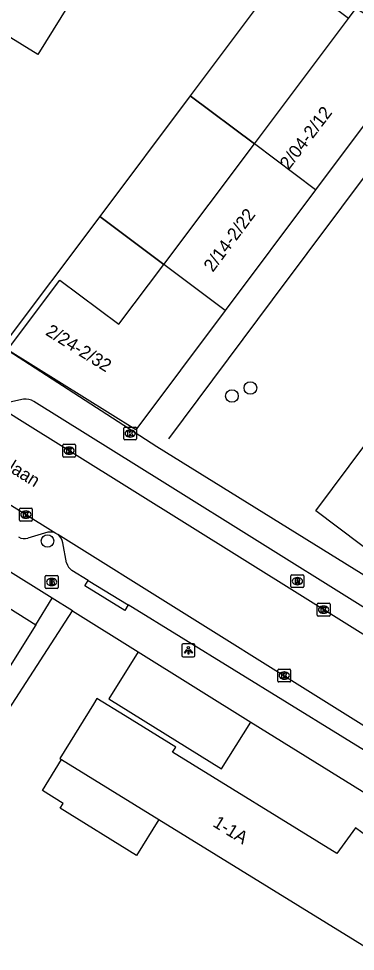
# Model space of a CAD drawing. Extents: x 160107 to 160928, y 382056 to 382918.
# Drawn here: x 160634.2 to 160660.5, y 382444.7 to 382517.3 of the extents above; entities that cross this region are included whole.
import ezdxf

# ---------------------------------------------------------------- set-up
doc = ezdxf.new("R2010")
doc.units = 0
for name, color, linetype in [('IMGEO_Boom', 7, 'Continuous'), ('IMGEO_Brandkraan', 7, 'Continuous'), ('IMGEO_Kolk', 7, 'Continuous'), ('IMGEO_Lichtpunt', 7, 'Continuous'), ('IMGEO_Lijnafwatering', 7, 'Continuous'), ('IMGEO_Openbare_ruimte_label', 7, 'Continuous'), ('IMGEO_Pand', 7, 'Continuous'), ('IMGEO_Pand_nummerreeks', 7, 'Continuous'), ('IMGEO_Pand_overbouw', 7, 'Continuous'), ('IMGEO_Rijbaan_lokaal_open', 7, 'Continuous'), ('IMGEO_Rioolput', 7, 'Continuous'), ('IMGEO_Voetpad_open', 7, 'Continuous')]:
    doc.layers.add(name, color=color, linetype=linetype)

msp = doc.modelspace()

# ---------------------------------------------------------------- linework, layer by layer
at = {"layer": 'IMGEO_Boom'}
for centre in [(160652.272, 382488.556), (160650.828, 382487.928), (160636.455, 382476.634)]:
    msp.add_circle(centre, 0.489, dxfattribs=at)
at = {"layer": 'IMGEO_Brandkraan'}
for p, q in [((160636.278, 382473.007), (160636.278, 382473.859)), ((160636.353, 382473.933), (160637.205, 382473.933)), ((160636.766, 382473.713), (160636.791, 382473.713)), ((160637.279, 382473.859), (160637.279, 382473.007)), ((160637.205, 382472.933), (160636.353, 382472.933)), ((160636.789, 382473.153), (160636.764, 382473.153))]:
    msp.add_line(p, q, dxfattribs=at)
for points in [[(160636.278, 382473.007), (160636.278, 382473.859)], [(160636.353, 382473.933), (160637.205, 382473.933)], [(160636.626, 382473.633), (160636.626, 382473.233), (160636.839, 382473.233)], [(160636.857, 382473.633), (160636.626, 382473.633)], [(160636.805, 382473.552), (160636.751, 382473.552), (160636.751, 382473.476)], [(160636.751, 382473.476), (160636.804, 382473.476)], [(160636.813, 382473.4), (160636.751, 382473.4), (160636.751, 382473.319)], [(160636.751, 382473.319), (160636.813, 382473.319)], [(160637.279, 382473.859), (160637.279, 382473.007)], [(160637.205, 382472.933), (160636.353, 382472.933)]]:
    msp.add_lwpolyline(points, dxfattribs=at)
for centre, radius, start, end in [((160636.355, 382473.857), 0.0765, 91.55205, 178.44795), ((160636.355, 382473.857), 0.0765, 91.55205, 178.44795), ((160636.806, 382473.514), 0.0379, 267.82845, 90.93552), ((160636.814, 382473.359), 0.0404, 269.87594, 90.50774), ((160636.861, 382473.488), 0.145, 59.4692, 91.53667), ((160636.886, 382473.535), 0.0922, 285.51372, 58.15012), ((160636.891, 382473.343), 0.105, 301.31148, 78.98903), ((160637.203, 382473.857), 0.0765, 1.55205, 88.44795), ((160637.203, 382473.857), 0.0765, 1.55205, 88.44795), ((160636.355, 382473.009), 0.0765, 181.55205, 268.44795), ((160636.355, 382473.009), 0.0765, 181.55205, 268.44795), ((160636.845, 382473.484), 0.251, 268.66757, 293.53466), ((160637.203, 382473.009), 0.0765, 271.55205, 358.44795), ((160637.203, 382473.009), 0.0765, 271.55205, 358.44795)]:
    msp.add_arc(centre, radius, start, end, dxfattribs=at)
for centre, major_axis, ratio, start_param, end_param in [((160636.765, 382473.433), (-0.387, 0.002), 0.722429, 4.712389, 7.853982), ((160636.79, 382473.433), (-0.39, 0.002), 0.717154, 1.570796, 4.712389)]:
    msp.add_ellipse(centre, major_axis=major_axis, ratio=ratio, start_param=start_param, end_param=end_param, dxfattribs=at)
at = {"layer": 'IMGEO_Kolk'}
for p, q in [((160642.398, 382484.582), (160642.398, 382485.434)), ((160642.473, 382485.508), (160643.325, 382485.508)), ((160642.886, 382485.288), (160642.911, 382485.288)), ((160643.399, 382485.434), (160643.399, 382484.582)), ((160643.325, 382484.508), (160642.473, 382484.508)), ((160642.909, 382484.728), (160642.884, 382484.728)), ((160637.641, 382483.241), (160637.641, 382484.093)), ((160637.716, 382484.167), (160638.568, 382484.167)), ((160638.129, 382483.947), (160638.154, 382483.947)), ((160638.642, 382484.093), (160638.642, 382483.241)), ((160638.568, 382483.167), (160637.716, 382483.167)), ((160638.152, 382483.387), (160638.127, 382483.387)), ((160634.266, 382478.263), (160634.266, 382479.115)), ((160634.341, 382479.189), (160635.193, 382479.189)), ((160635.267, 382479.115), (160635.267, 382478.263)), ((160634.777, 382478.409), (160634.752, 382478.409)), ((160634.754, 382478.969), (160634.779, 382478.969)), ((160635.193, 382478.189), (160634.341, 382478.189)), ((160657.478, 382470.854), (160657.478, 382471.706)), ((160657.553, 382471.78), (160658.405, 382471.78)), ((160657.966, 382471.56), (160657.991, 382471.56)), ((160658.479, 382471.706), (160658.479, 382470.854)), ((160658.405, 382470.78), (160657.553, 382470.78)), ((160657.989, 382471), (160657.964, 382471)), ((160654.404, 382465.72), (160654.404, 382466.572)), ((160654.479, 382466.646), (160655.331, 382466.646)), ((160654.892, 382466.426), (160654.917, 382466.426)), ((160655.405, 382466.572), (160655.405, 382465.72)), ((160655.331, 382465.646), (160654.479, 382465.646)), ((160654.915, 382465.866), (160654.89, 382465.866))]:
    msp.add_line(p, q, dxfattribs=at)
for points in [[(160642.398, 382484.582), (160642.398, 382485.434)], [(160642.473, 382485.508), (160643.325, 382485.508)], [(160642.719, 382485.208), (160642.842, 382485.208), (160642.842, 382485.057), (160642.972, 382485.208), (160643.136, 382485.208), (160642.99, 382485.057), (160643.143, 382484.808), (160642.991, 382484.808), (160642.906, 382484.972), (160642.842, 382484.905), (160642.842, 382484.808), (160642.719, 382484.808), (160642.719, 382485.208)], [(160643.399, 382485.434), (160643.399, 382484.582)], [(160643.325, 382484.508), (160642.473, 382484.508)], [(160637.641, 382483.241), (160637.641, 382484.093)], [(160637.716, 382484.167), (160638.568, 382484.167)], [(160637.962, 382483.867), (160638.085, 382483.867), (160638.085, 382483.716), (160638.215, 382483.867), (160638.379, 382483.867), (160638.233, 382483.716), (160638.386, 382483.467), (160638.234, 382483.467), (160638.149, 382483.631), (160638.085, 382483.564), (160638.085, 382483.467), (160637.962, 382483.467), (160637.962, 382483.867)], [(160638.642, 382484.093), (160638.642, 382483.241)], [(160638.568, 382483.167), (160637.716, 382483.167)], [(160634.266, 382478.263), (160634.266, 382479.115)], [(160634.341, 382479.189), (160635.193, 382479.189)], [(160635.267, 382479.115), (160635.267, 382478.263)], [(160634.587, 382478.889), (160634.71, 382478.889), (160634.71, 382478.738), (160634.84, 382478.889), (160635.004, 382478.889), (160634.858, 382478.738), (160635.011, 382478.489), (160634.859, 382478.489), (160634.774, 382478.653), (160634.71, 382478.586), (160634.71, 382478.489), (160634.587, 382478.489), (160634.587, 382478.889)], [(160635.193, 382478.189), (160634.341, 382478.189)], [(160657.478, 382470.854), (160657.478, 382471.706)], [(160657.553, 382471.78), (160658.405, 382471.78)], [(160657.799, 382471.48), (160657.922, 382471.48), (160657.922, 382471.329), (160658.052, 382471.48), (160658.216, 382471.48), (160658.07, 382471.329), (160658.223, 382471.08), (160658.071, 382471.08), (160657.986, 382471.244), (160657.922, 382471.177), (160657.922, 382471.08), (160657.799, 382471.08), (160657.799, 382471.48)], [(160658.479, 382471.706), (160658.479, 382470.854)], [(160658.405, 382470.78), (160657.553, 382470.78)], [(160654.404, 382465.72), (160654.404, 382466.572)], [(160654.479, 382466.646), (160655.331, 382466.646)], [(160654.725, 382466.346), (160654.848, 382466.346), (160654.848, 382466.195), (160654.978, 382466.346), (160655.142, 382466.346), (160654.996, 382466.195), (160655.149, 382465.946), (160654.997, 382465.946), (160654.912, 382466.11), (160654.848, 382466.043), (160654.848, 382465.946), (160654.725, 382465.946), (160654.725, 382466.346)], [(160655.405, 382466.572), (160655.405, 382465.72)], [(160655.331, 382465.646), (160654.479, 382465.646)]]:
    msp.add_lwpolyline(points, dxfattribs=at)
for centre, start, end in [((160642.475, 382485.432), 91.55205, 178.44795), ((160642.475, 382485.432), 91.55205, 178.44795), ((160643.323, 382485.432), 1.55205, 88.44795), ((160643.323, 382485.432), 1.55205, 88.44795), ((160642.475, 382484.584), 181.55205, 268.44795), ((160642.475, 382484.584), 181.55205, 268.44795), ((160643.323, 382484.584), 271.55205, 358.44795), ((160643.323, 382484.584), 271.55205, 358.44795), ((160637.718, 382484.091), 91.55205, 178.44795), ((160637.718, 382484.091), 91.55205, 178.44795), ((160638.566, 382484.091), 1.55205, 88.44795), ((160638.566, 382484.091), 1.55205, 88.44795), ((160637.718, 382483.243), 181.55205, 268.44795), ((160637.718, 382483.243), 181.55205, 268.44795), ((160638.566, 382483.243), 271.55205, 358.44795), ((160638.566, 382483.243), 271.55205, 358.44795), ((160634.343, 382479.113), 91.55205, 178.44795), ((160634.343, 382479.113), 91.55205, 178.44795), ((160635.191, 382479.113), 1.55205, 88.44795), ((160635.191, 382479.113), 1.55205, 88.44795), ((160634.343, 382478.265), 181.55205, 268.44795), ((160634.343, 382478.265), 181.55205, 268.44795), ((160635.191, 382478.265), 271.55205, 358.44795), ((160635.191, 382478.265), 271.55205, 358.44795), ((160657.555, 382471.704), 91.55205, 178.44795), ((160657.555, 382471.704), 91.55205, 178.44795), ((160658.403, 382471.704), 1.55205, 88.44795), ((160658.403, 382471.704), 1.55205, 88.44795), ((160657.555, 382470.856), 181.55205, 268.44795), ((160657.555, 382470.856), 181.55205, 268.44795), ((160658.403, 382470.856), 271.55205, 358.44795), ((160658.403, 382470.856), 271.55205, 358.44795), ((160654.481, 382466.57), 91.55205, 178.44795), ((160654.481, 382466.57), 91.55205, 178.44795), ((160655.329, 382466.57), 1.55205, 88.44795), ((160655.329, 382466.57), 1.55205, 88.44795), ((160654.481, 382465.722), 181.55205, 268.44795), ((160654.481, 382465.722), 181.55205, 268.44795), ((160655.329, 382465.722), 271.55205, 358.44795), ((160655.329, 382465.722), 271.55205, 358.44795)]:
    msp.add_arc(centre, 0.0765, start, end, dxfattribs=at)
for centre, major_axis, ratio, start_param, end_param in [((160642.885, 382485.008), (-0.387, 0.002), 0.722429, 4.712389, 7.853982), ((160642.91, 382485.008), (-0.39, 0.002), 0.717154, 1.570796, 4.712389), ((160638.128, 382483.667), (-0.387, 0.002), 0.722429, 4.712389, 7.853982), ((160638.153, 382483.667), (-0.39, 0.002), 0.717154, 1.570796, 4.712389), ((160634.753, 382478.689), (-0.387, 0.002), 0.722429, 4.712389, 7.853982), ((160634.778, 382478.689), (-0.39, 0.002), 0.717154, 1.570796, 4.712389), ((160657.965, 382471.28), (-0.387, 0.002), 0.722429, 4.712389, 7.853982), ((160657.99, 382471.28), (-0.39, 0.002), 0.717154, 1.570796, 4.712389), ((160654.891, 382466.146), (-0.387, 0.002), 0.722429, 4.712389, 7.853982), ((160654.916, 382466.146), (-0.39, 0.002), 0.717154, 1.570796, 4.712389)]:
    msp.add_ellipse(centre, major_axis=major_axis, ratio=ratio, start_param=start_param, end_param=end_param, dxfattribs=at)
at = {"layer": 'IMGEO_Lichtpunt'}
for p, q in [((160646.935, 382468.517), (160646.935, 382467.71)), ((160646.935, 382468.517), (160646.935, 382467.71)), ((160647.837, 382468.612), (160647.029, 382468.612)), ((160647.837, 382468.612), (160647.029, 382468.612)), ((160647.931, 382467.71), (160647.931, 382468.517)), ((160647.931, 382467.71), (160647.931, 382468.517)), ((160647.029, 382467.616), (160647.837, 382467.616)), ((160647.029, 382467.616), (160647.837, 382467.616))]:
    msp.add_line(p, q, dxfattribs=at)
for points in [[(160647.309, 382468.181), (160647.348, 382468.153), (160647.16, 382467.891), (160647.122, 382467.918), (160647.309, 382468.181)], [(160647.411, 382468.133), (160647.458, 382468.133), (160647.458, 382467.811), (160647.411, 382467.811), (160647.411, 382468.133)], [(160647.521, 382468.153), (160647.559, 382468.18), (160647.746, 382467.918), (160647.707, 382467.89), (160647.521, 382468.153)]]:
    msp.add_lwpolyline(points, dxfattribs=at)
msp.add_circle((160647.434, 382468.315), 0.0994, dxfattribs=at)
for centre, start, end in [((160647.029, 382468.517), 90, 180), ((160647.029, 382468.517), 90, 180), ((160647.837, 382468.517), 0, 90), ((160647.837, 382468.517), 0, 90), ((160647.029, 382467.71), 180, 270), ((160647.029, 382467.71), 180, 270), ((160647.837, 382467.71), 270, 0), ((160647.837, 382467.71), 270, 360)]:
    msp.add_arc(centre, 0.0946, start, end, dxfattribs=at)
at = {"layer": 'IMGEO_Lijnafwatering'}
for points in [[(160654, 382495.426), (160662.091, 382506.254)], [(160645.91, 382484.597), (160654, 382495.426)]]:
    msp.add_lwpolyline(points, dxfattribs=at)
at = {"layer": 'IMGEO_Pand'}
for points in [[(160639.295, 382520.324), (160635.687, 382514.541), (160633.257, 382516.056), (160631.03, 382517.445), (160622.018, 382503.2), (160622.561, 382502.857), (160622.454, 382502.688), (160623.206, 382502.212), (160623.035, 382501.942), (160616.467, 382506.097), (160618.877, 382509.909), (160617.058, 382511.061), (160621.744, 382518.47)], [(160652.582, 382507.572), (160659.926, 382517.347), (160660.526, 382518.146), (160665.515, 382514.919)], [(160662.14, 382510.411), (160657.342, 382504.002)], [(160645.524, 382498.178), (160652.582, 382507.572)], [(160657.342, 382504.002), (160652.582, 382507.572)], [(160657.342, 382504.002), (160650.301, 382494.596)], [(160650.301, 382494.596), (160643.343, 382485.301), (160633.336, 382491.531), (160637.422, 382496.967), (160642.026, 382493.523), (160645.524, 382498.178)], [(160650.301, 382494.596), (160645.524, 382498.178)], [(160667.761, 382492.911), (160677.503, 382485.613), (160681.492, 382482.598), (160673.677, 382472.259), (160667.015, 382477.296), (160664.325, 382473.736), (160657.378, 382478.987), (160667.761, 382492.911)], [(160630.808, 382473.047), (160635.54, 382470.101)], [(160635.54, 382470.101), (160632.891, 382465.866), (160630.784, 382462.498), (160629.877, 382461.047)], [(160643.528, 382467.993), (160641.229, 382464.322), (160650.03, 382458.884), (160652.296, 382462.502)], [(160643.528, 382467.993), (160652.296, 382462.502)], [(160664.677, 382454.86), (160662.926, 382452.473), (160660.47, 382454.274), (160659.015, 382452.289), (160646.208, 382460.179), (160646.451, 382460.573), (160642.506, 382463.004), (160640.309, 382464.367), (160640.037, 382463.924), (160637.426, 382459.686), (160637.554, 382459.607)], [(160645.131, 382454.939), (160643.4, 382452.129), (160637.44, 382455.801), (160637.676, 382456.184), (160636.059, 382457.181), (160637.554, 382459.607)], [(160637.554, 382459.607), (160645.131, 382454.939)], [(160645.131, 382454.939), (160666.802, 382441.589)]]:
    msp.add_lwpolyline(points, dxfattribs=at)
at = {"layer": 'IMGEO_Pand_overbouw'}
for points in [[(160652.582, 382507.572), (160659.926, 382517.347), (160654.91, 382521.109), (160647.574, 382511.327)], [(160652.582, 382507.572), (160647.574, 382511.327), (160640.525, 382501.927), (160645.524, 382498.178)], [(160633.336, 382491.531), (160637.422, 382496.967), (160642.026, 382493.523), (160645.524, 382498.178), (160640.525, 382501.927), (160632.911, 382491.774)]]:
    msp.add_lwpolyline(points, close=True, dxfattribs=at)
at = {"layer": 'IMGEO_Rijbaan_lokaal_open'}
for points in [[(160637.113, 382477.217), (160615.673, 382490.566)], [(160631.794, 382487.669), (160634.056, 382486.236), (160669.392, 382464.183)], [(160637.252, 382477.13), (160637.113, 382477.217)], [(160666.192, 382459.055), (160637.252, 382477.13)]]:
    msp.add_lwpolyline(points, dxfattribs=at)
at = {"layer": 'IMGEO_Rioolput'}
for p, q in [((160655.43, 382473.073), (160655.43, 382473.925)), ((160655.505, 382473.999), (160656.357, 382473.999)), ((160655.918, 382473.779), (160655.943, 382473.779)), ((160656.431, 382473.925), (160656.431, 382473.073)), ((160656.357, 382472.999), (160655.505, 382472.999)), ((160655.941, 382473.219), (160655.916, 382473.219))]:
    msp.add_line(p, q, dxfattribs=at)
for points in [[(160655.43, 382473.073), (160655.43, 382473.925)], [(160655.505, 382473.999), (160656.357, 382473.999)], [(160656.019, 382473.697), (160655.767, 382473.699), (160655.767, 382473.299)], [(160655.767, 382473.299), (160655.891, 382473.299), (160655.891, 382473.461), (160655.902, 382473.461)], [(160655.945, 382473.618), (160655.891, 382473.618), (160655.891, 382473.537)], [(160655.891, 382473.537), (160655.943, 382473.537)], [(160655.949, 382473.432), (160656.02, 382473.299), (160656.16, 382473.299), (160656.095, 382473.425)], [(160656.431, 382473.925), (160656.431, 382473.073)], [(160656.357, 382472.999), (160655.505, 382472.999)]]:
    msp.add_lwpolyline(points, dxfattribs=at)
for centre, radius, start, end in [((160655.507, 382473.923), 0.0765, 91.55205, 178.44795), ((160655.507, 382473.923), 0.0765, 91.55205, 178.44795), ((160655.901, 382473.408), 0.0533, 26.02933, 88.69889), ((160655.927, 382473.726), 0.19, 274.7715, 282.96867), ((160655.951, 382473.522), 0.0964, 77.00612, 93.18647), ((160655.965, 382473.579), 0.0378, 276.66336, 79.67722), ((160656.018, 382473.587), 0.109, 350.36119, 89.41601), ((160656.016, 382473.587), 0.112, 277.58423, 350.98172), ((160656, 382473.372), 0.108, 29.51342, 73.79051), ((160656.355, 382473.923), 0.0765, 1.55205, 88.44795), ((160656.355, 382473.923), 0.0765, 1.55205, 88.44795), ((160655.507, 382473.075), 0.0765, 181.55205, 268.44795), ((160655.507, 382473.075), 0.0765, 181.55205, 268.44795), ((160656.355, 382473.075), 0.0765, 271.55205, 358.44795), ((160656.355, 382473.075), 0.0765, 271.55205, 358.44795)]:
    msp.add_arc(centre, radius, start, end, dxfattribs=at)
for centre, major_axis, ratio, start_param, end_param in [((160655.917, 382473.499), (-0.387, 0.002), 0.722429, 4.712389, 7.853982), ((160655.942, 382473.499), (-0.39, 0.002), 0.717154, 1.570796, 4.712389)]:
    msp.add_ellipse(centre, major_axis=major_axis, ratio=ratio, start_param=start_param, end_param=end_param, dxfattribs=at)
at = {"layer": 'IMGEO_Voetpad_open'}
for points in [[(160636.83, 382472.17), (160592.202, 382500), (160588.519, 382502.294), (160565.683, 382503.748)], [(160620.525, 382499.569), (160632.911, 382491.774), (160644.968, 382483.985), (160680.935, 382461.701)], [(160634.592, 382487.675), (160633.277, 382487.396)], [(160667.829, 382467.255), (160645.589, 382481.125), (160635.377, 382487.506)], [(160636.472, 382477.312), (160634.933, 382476.85)], [(160637.947, 382474.938), (160637.646, 382476.479)], [(160639.623, 382473.562), (160638.362, 382474.339)], [(160642.736, 382471.644), (160642.474, 382471.219), (160639.361, 382473.137), (160639.623, 382473.562)], [(160639.623, 382473.562), (160642.736, 382471.644)], [(160635.54, 382470.101), (160636.83, 382472.17)], [(160638.41, 382471.185), (160636.83, 382472.17)], [(160630.34, 382458.764), (160638.41, 382471.185)], [(160638.41, 382471.185), (160643.528, 382467.993)], [(160663.389, 382458.917), (160642.736, 382471.644)], [(160652.296, 382462.502), (160664.677, 382454.86)]]:
    msp.add_lwpolyline(points, dxfattribs=at)
for centre, radius, start, end in [((160634.771, 382486.599), 1.091, 56.24854, 99.45231), ((160634.675, 382477.71), 0.898, 238.33184, 286.66425), ((160636.654, 382476.33), 0.999, 62.63777, 100.50181), ((160636.636, 382476.312), 1.024, 9.36968, 52.99688), ((160638.84, 382475.113), 0.91, 191.10617, 238.32392)]:
    msp.add_arc(centre, radius, start, end, dxfattribs=at)

# ---------------------------------------------------------------- texts
at = {"layer": 'IMGEO_Openbare_ruimte_label'}
msp.add_text('Philips de Goedelaan', height=1, rotation=328.2498, dxfattribs=at).set_placement((160624.653, 382487.486))
at = {"layer": 'IMGEO_Pand_nummerreeks'}
for s, rotation, p in [('2/04-2/12', 52.59842, (160655.267, 382505.512)), ('2/14-2/22', 53.30129, (160649.34, 382497.526)), ('2/24-2/32', 328.07849, (160636.234, 382492.738)), ('1-1A', 328.36127, (160649.273, 382454.439))]:
    msp.add_text(s, height=1, rotation=rotation, dxfattribs=at).set_placement(p)

doc.saveas('drawing.dxf')
